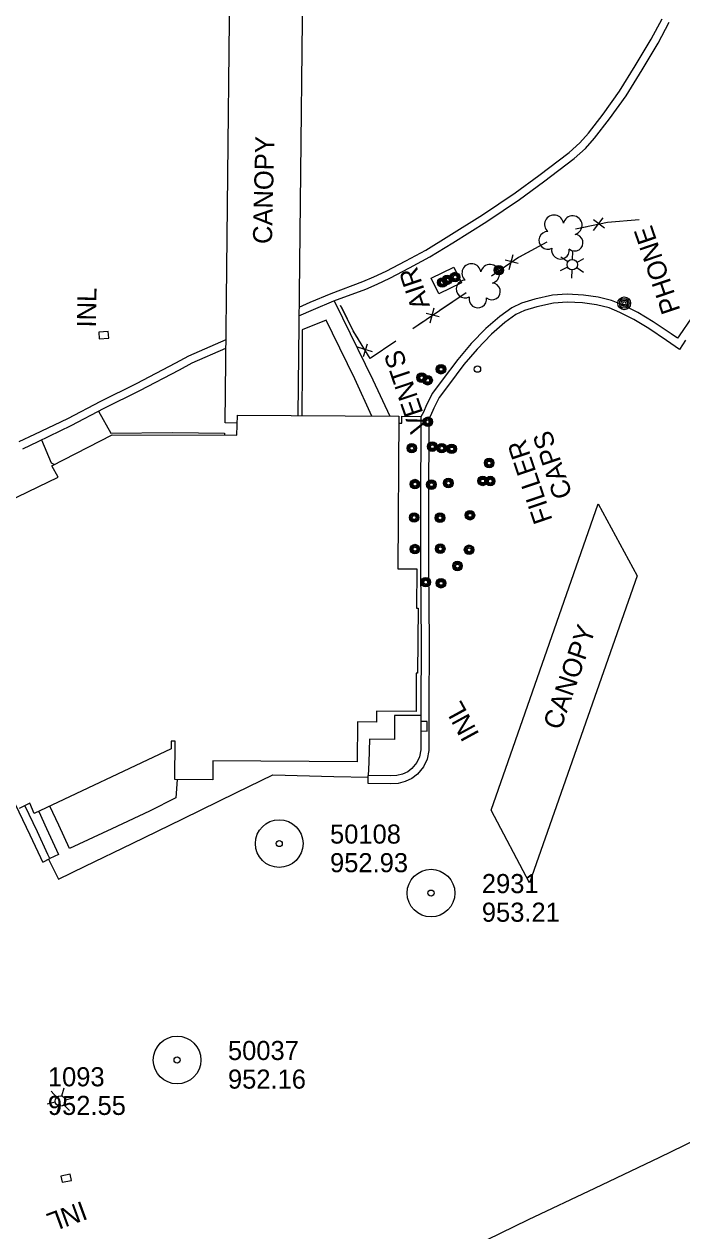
# Model space of a CAD drawing. Extents: x 353423 to 364002, y 127000 to 201942.
# Drawn here: x 358350.6 to 358557.6, y 132514.4 to 132893.9 of the extents above; entities that cross this region are included whole.
import ezdxf

# ---------------------------------------------------------------- set-up
doc = ezdxf.new("R2010")
doc.units = 0
for name, color, linetype in [('E_DTM_SlopeBottom', 7, 'Continuous'), ('E_FEN_Generic', 7, 'Continuous'), ('E_LAND_BrushLine', 7, 'Continuous'), ('E_MISCPROP', 7, 'Continuous'), ('E_RDWY_AsphConc', 7, 'Continuous'), ('E_UTL_ETransformer', 7, 'Continuous'), ('E_WTR_FlowLine', 7, 'Continuous')]:
    doc.layers.add(name, color=color, linetype=linetype)

msp = doc.modelspace()

# ---------------------------------------------------------------- linework, layer by layer
at = {"layer": 'E_DTM_SlopeBottom'}
for p, q in [((358532.67, 132832.95), (358529.69, 132829.02)), ((358533.16, 132829.74), (358529.78, 132832.28)), ((358504.39, 132821.34), (358503.16, 132816.56)), ((358506.08, 132818.57), (358501.98, 132819.6)), ((358481.18, 132801.8), (358477.09, 132802.88)), ((358479.52, 132804.58), (358478.23, 132799.82)), ((358460.23, 132790.86), (358455.53, 132792.34)), ((358457.38, 132789.31), (358458.63, 132793.35))]:
    msp.add_line(p, q, dxfattribs=at)
for points in [[(358544.08, 132832.32), (358534.2, 132831.49), (358524.13, 132829.41)], [(358544.08, 132832.32), (358534.2, 132831.49), (358534.16, 132831.48)], [(358527.71, 132830.15), (358524.13, 132829.41)], [(358515.08, 132825.32), (358506.17, 132820.45), (358497.64, 132814.59)], [(358515.08, 132825.32), (358506.34, 132820.54)], [(358500.9, 132816.83), (358497.64, 132814.59)], [(358489.72, 132809.33), (358472.88, 132798.04)], [(358489.72, 132809.33), (358481.45, 132803.78)], [(358467.52, 132794.17), (358459.49, 132788.74), (358454.18, 132797.43), (358450.19, 132805.43)], [(358450.62, 132804.57), (358450.19, 132805.43)], [(358455.92, 132794.58), (358454.18, 132797.43), (358450.62, 132804.57)], [(358475.98, 132800.12), (358472.88, 132798.04)], [(358377.21, 132795.17), (358377.07, 132797.17), (358374.08, 132796.96), (358374.22, 132794.96), (358377.21, 132795.17)], [(358467.52, 132794.17), (358459.49, 132788.74), (358459.35, 132788.96)], [(358477.44, 132674.59), (358475.44, 132674.6), (358475.42, 132671.6), (358477.42, 132671.59), (358477.44, 132674.59)], [(358365.49, 132530.24), (358365.13, 132532.2), (358362.18, 132531.66), (358362.54, 132529.69), (358365.49, 132530.24)]]:
    msp.add_lwpolyline(points, dxfattribs=at)
msp.add_lwpolyline([(358478.64, 132813.95), (358485.79, 132817.46), (358488.21, 132812.52), (358481.06, 132809.02)], close=True, dxfattribs=at)
at = {"layer": 'E_FEN_Generic'}
for centre, radius, start, end in [((358517.33, 132830.87), 2.97, 7.0782, 228.3121), ((358523.18, 132830.63), 2.97, 284.7291, 167.7023), ((358515.36, 132825.88), 2.78, 90.0491, 297.8221), ((358523.82, 132825.14), 2.61, 229.4343, 87.3669), ((358519.36, 132822.78), 2.78, 166.7261, 7.7372), ((358491.33, 132815.56), 2.97, 7.0782, 228.3121), ((358497.18, 132815.31), 2.97, 284.7291, 167.7023), ((358489.35, 132810.56), 2.78, 90.0491, 297.8221), ((358497.81, 132809.82), 2.61, 229.4343, 87.3669), ((358493.36, 132807.46), 2.78, 166.7261, 7.7372)]:
    msp.add_arc(centre, radius, start, end, dxfattribs=at)
at = {"layer": 'E_LAND_BrushLine'}
for p, q in [((358523.12, 132819.87), (358523.25, 132822.39)), ((358521.61, 132817.47), (358519.28, 132816.33)), ((358521.66, 132819.17), (358519.46, 132820.59)), ((358524.46, 132817.32), (358526.62, 132815.91)), ((358524.54, 132818.96), (358526.75, 132820.15)), ((358522.95, 132816.6), (358522.82, 132814)), ((358362.5, 132556.83), (358363.23, 132559.35)), ((358360.86, 132556.4), (358359.1, 132558.31)), ((358363.59, 132555.63), (358366.04, 132556.23)), ((358360.41, 132554.86), (358357.88, 132554.25)), ((358361.53, 132553.62), (358360.79, 132551.15)), ((358363.12, 132554.01), (358364.89, 132552.23))]:
    msp.add_line(p, q, dxfattribs=at)
for centre, radius in [((358523.06, 132818.23), 1.64), ((358539.42, 132806.09), 2.02), ((358539.41, 132806.09), 1.52), ((358539.45, 132806.1), 1.01), ((358539.44, 132806.1), 0.502), ((358362, 132555.23), 1.64)]:
    msp.add_circle(centre, radius, dxfattribs=at)
at = {"layer": 'E_MISCPROP'}
for points in [[(358437.08, 132802.11), (358441.6, 132804.13), (358448.08, 132806.83), (358458.12, 132810.57), (358461.7, 132812.11), (358465.66, 132813.98), (358471.85, 132817.19), (358478.26, 132820.67), (358485.52, 132825.13), (358496.17, 132831.84), (358506.5, 132838.73), (358514.05, 132844.23), (358523.68, 132851.58), (358527.24, 132854.8), (358530.08, 132857.98), (358534.83, 132864.04), (358540.04, 132871.36), (358545.04, 132879.45), (358550.1, 132887.92), (358553.59, 132894.45)], [(358437.11, 132804.87), (358440.61, 132806.43), (358447.16, 132809.15), (358457.19, 132812.89), (358460.67, 132814.39), (358464.55, 132816.22), (358470.67, 132819.4), (358477.01, 132822.84), (358484.2, 132827.25), (358494.81, 132833.94), (358505.07, 132840.78), (358512.55, 132846.24), (358522.08, 132853.5), (358525.46, 132856.57), (358528.16, 132859.59), (358532.83, 132865.54), (358537.96, 132872.74), (358542.91, 132880.75), (358547.92, 132889.15), (358551.34, 132895.54)], [(358448.16, 132806.86), (358450.77, 132801.46), (358460.3, 132782.06), (358465.71, 132770.6)], [(358558.73, 132794.45), (358556.83, 132791.58), (358552.76, 132794.36), (358547.14, 132798.17), (358542.45, 132801), (358538.05, 132803.22), (358534.65, 132804.62), (358530.73, 132805.57), (358526.34, 132806.18), (358521.49, 132806.47), (358517.18, 132806.13), (358511.91, 132805), (358507.99, 132803.82), (358505.34, 132802.53), (358501.82, 132800), (358497.64, 132796.33), (358493.14, 132791.71), (358489, 132786.86), (358484.08, 132780.39), (358481.19, 132776.51), (358479.48, 132773.12), (358478.49, 132770.74), (358477.94, 132769.73), (358477.93, 132766.43), (358477.85, 132745.7), (358477.79, 132722.84), (358478.05, 132699.46), (358477.97, 132678.72), (358477.93, 132673.32), (358477.91, 132665.48), (358477.4, 132662.75), (358476.28, 132660.33), (358474.39, 132657.98), (358472.56, 132656.63), (358470.49, 132655.67), (358468.28, 132655.11), (358466.03, 132655.02), (358458.82, 132655.09), (358458.84, 132657.59)], [(358560.57, 132801.47), (358556.66, 132795.85), (358556.15, 132795.07), (358554.17, 132796.43), (358548.49, 132800.28), (358543.66, 132803.19), (358539.09, 132805.49), (358535.43, 132807.01), (358531.19, 132808.03), (358526.59, 132808.67), (358521.47, 132808.98), (358516.82, 132808.61), (358511.29, 132807.43), (358507.07, 132806.16), (358504.05, 132804.68), (358500.26, 132801.95), (358495.92, 132798.14), (358491.29, 132793.4), (358487.05, 132788.43), (358482.08, 132781.89), (358479.06, 132777.83), (358477.21, 132774.16), (358476.23, 132771.82), (358475.44, 132770.36), (358475.43, 132766.43), (358475.35, 132745.71), (358475.29, 132722.83), (358475.55, 132699.46), (358475.47, 132678.74), (358475.43, 132673.33), (358475.41, 132665.72), (358475, 132663.52), (358474.14, 132661.66), (358472.64, 132659.8), (358471.28, 132658.79), (358469.65, 132658.04), (358467.91, 132657.59), (358465.99, 132657.52), (358458.84, 132657.59)], [(358459.99, 132770.64), (358454.7, 132782.29), (358447.67, 132796.68), (358445.65, 132800.8), (358438.04, 132797.79), (358438.12, 132786.15), (358437.96, 132770.79)], [(358398.3, 132787.4), (358402.37, 132789.58), (358414.13, 132794.73)], [(358399.47, 132785.2), (358403.46, 132787.32), (358414.1, 132791.98)], [(358349.06, 132762.58), (358353.93, 132764.89), (358364.31, 132769.86), (358374.69, 132775.32), (358385.91, 132780.9), (358398.31, 132787.41)], [(358350.19, 132760.35), (358355.01, 132762.63), (358365.43, 132767.63), (358375.83, 132773.1), (358387.04, 132778.68), (358399.47, 132785.2)], [(358374.02, 132772.14), (358377.92, 132765.21), (358397.23, 132765.42)], [(358468.53, 132768.35), (358469.49, 132768.34), (358469.48, 132770.6), (358475.5, 132770.46)], [(358397.23, 132765.42), (358413.65, 132765.25), (358413.62, 132764.58)], [(358356.03, 132763.12), (358359.07, 132755.87), (358360.15, 132755.42)], [(358475.45, 132676.5), (358467.13, 132676.48), (358467.11, 132668.93), (358459.28, 132669.07), (358459.04, 132661.68), (358458.84, 132657.59)], [(358356.48, 132630.37), (358355.81, 132631.7), (358352.52, 132638.85), (358346.75, 132650.94), (358342.83, 132659.44), (358339.86, 132665.43)], [(358400.48, 132643.93), (358417.43, 132652.29), (358428.83, 132657.77), (358448.01, 132657.33), (358458.84, 132657.09)], [(358398.77, 132656.35), (358398.36, 132650.54), (358390.01, 132646.36), (358378.21, 132640.8), (358364.9, 132634.64), (358361.54, 132642.02), (358358.71, 132647.99)], [(358356.48, 132630.37), (358358.71, 132631.49), (358358.06, 132632.78), (358354.78, 132639.91), (358350.84, 132648.17)], [(358355.19, 132646.33), (358357.67, 132640.9), (358361.4, 132632.81), (358358.71, 132631.49)], [(358358.26, 132631.27), (358361.43, 132625.05), (358369.82, 132629.07), (358384.54, 132636.22), (358400.48, 132643.93)], [(358401.35, 132465.83), (358421.21, 132475.14), (358447.67, 132488.04), (358469.88, 132498.6), (358491.87, 132509.5), (358509.27, 132517.94), (358530.2, 132527.85), (358550.67, 132537.59), (358569.86, 132546.9), (358589, 132555.99), (358607.79, 132564.98), (358625.03, 132573.36), (358635.49, 132578.04), (358639.01, 132579.73), (358643.78, 132582.85), (358652.7, 132589.43), (358657.24, 132593.33), (358660.23, 132597.03), (358665.84, 132605.99), (358673.95, 132620.21), (358675.37, 132622.86), (358675.49, 132623.86), (358675.13, 132626.43), (358673.22, 132639.8)]]:
    msp.add_lwpolyline(points, dxfattribs=at)
at = {"layer": 'E_RDWY_AsphConc'}
for centre, radius in [((358430.85, 132636.19), 7.5), ((358430.85, 132636.19), 7.5), ((358430.85, 132636.19), 7.5), ((358430.85, 132636.19), 7.5), ((358430.85, 132636.19), 0.96), ((358430.85, 132636.19), 0.96), ((358430.85, 132636.19), 0.96), ((358430.85, 132636.19), 0.96), ((358478.62, 132620.62), 7.5), ((358478.62, 132620.62), 7.5), ((358478.62, 132620.62), 7.5), ((358478.62, 132620.62), 7.5), ((358478.62, 132620.62), 0.96), ((358478.62, 132620.62), 0.96), ((358478.62, 132620.62), 0.96), ((358478.62, 132620.62), 0.96), ((358398.73, 132568.14), 7.5), ((358398.73, 132568.14), 7.5), ((358398.73, 132568.14), 7.5), ((358398.73, 132568.14), 7.5), ((358398.73, 132568.14), 0.96), ((358398.73, 132568.14), 0.96), ((358398.73, 132568.14), 0.96), ((358398.73, 132568.14), 0.96)]:
    msp.add_circle(centre, radius, dxfattribs=at)
at = {"layer": 'E_UTL_ETransformer'}
for centre, radius in [((358499.96, 132816.51), 1.5), ((358499.96, 132816.52), 1.22), ((358499.97, 132816.51), 0.968), ((358499.98, 132816.48), 0.605), ((358482.19, 132812.63), 1.5), ((358482.19, 132812.64), 1.22), ((358482.2, 132812.63), 0.968), ((358482.21, 132812.6), 0.605), ((358483.69, 132813.43), 1.5), ((358483.69, 132813.44), 1.22), ((358483.7, 132813.43), 0.968), ((358483.71, 132813.4), 0.605), ((358486.18, 132814.33), 1.5), ((358486.19, 132814.33), 1.22), ((358486.2, 132814.32), 0.968), ((358486.21, 132814.3), 0.605), ((358481.77, 132785.34), 1.5), ((358475.68, 132782.7), 1.5), ((358475.68, 132782.7), 1.22), ((358475.69, 132782.7), 0.968), ((358475.7, 132782.67), 0.605), ((358477.55, 132781.89), 1.5), ((358477.55, 132781.89), 1.22), ((358477.56, 132781.89), 0.968), ((358481.77, 132785.35), 1.22), ((358481.79, 132785.34), 0.968), ((358481.79, 132785.31), 0.605), ((358477.57, 132781.86), 0.605), ((358477.64, 132768.84), 1.5), ((358477.64, 132768.85), 1.22), ((358477.66, 132768.84), 0.968), ((358477.66, 132768.81), 0.605), ((358472.58, 132760.53), 1.5), ((358472.58, 132760.54), 1.22), ((358472.6, 132760.53), 0.968), ((358472.6, 132760.5), 0.605), ((358479.03, 132761.02), 1.5), ((358479.04, 132761.02), 1.22), ((358479.05, 132761.01), 0.968), ((358479.05, 132760.99), 0.605), ((358481.99, 132760.54), 1.5), ((358482, 132760.54), 1.22), ((358482.01, 132760.54), 0.968), ((358482.01, 132760.51), 0.605), ((358485.13, 132760.32), 1.5), ((358485.13, 132760.32), 1.22), ((358485.14, 132760.31), 0.968), ((358485.15, 132760.29), 0.605), ((358496.92, 132755.87), 1.5), ((358496.93, 132755.88), 1.22), ((358496.94, 132755.87), 0.968), ((358496.94, 132755.84), 0.605), ((358473.57, 132749.24), 1.5), ((358473.58, 132749.24), 1.22), ((358473.59, 132749.23), 0.968), ((358473.59, 132749.21), 0.605), ((358478.74, 132749.06), 1.5), ((358478.75, 132749.07), 1.22), ((358478.76, 132749.06), 0.968), ((358478.76, 132749.03), 0.605), ((358484.09, 132749.57), 1.5), ((358484.1, 132749.57), 1.22), ((358484.11, 132749.56), 0.968), ((358484.12, 132749.53), 0.605), ((358494.88, 132750.23), 1.5), ((358494.88, 132750.23), 1.22), ((358494.89, 132750.22), 0.968), ((358494.9, 132750.2), 0.605), ((358497.25, 132750.19), 1.5), ((358497.25, 132750.19), 1.22), ((358497.26, 132750.18), 0.968), ((358497.27, 132750.16), 0.605), ((358473.31, 132738.73), 1.5), ((358473.31, 132738.73), 1.22), ((358473.32, 132738.72), 0.968), ((358473.33, 132738.7), 0.605), ((358481.45, 132738.67), 1.5), ((358481.45, 132738.67), 1.22), ((358481.46, 132738.67), 0.968), ((358481.47, 132738.64), 0.605), ((358490.87, 132739.44), 1.5), ((358490.88, 132739.45), 1.22), ((358490.89, 132739.44), 0.968), ((358490.9, 132739.41), 0.605), ((358473.56, 132728.8), 1.5), ((358473.56, 132728.8), 1.22), ((358473.58, 132728.8), 0.968), ((358481.53, 132728.92), 1.5), ((358481.54, 132728.92), 1.22), ((358481.55, 132728.91), 0.968), ((358490.6, 132728.59), 1.5), ((358490.6, 132728.6), 1.22), ((358473.58, 132728.77), 0.605), ((358481.56, 132728.89), 0.605), ((358490.62, 132728.59), 0.968), ((358490.62, 132728.56), 0.605), ((358486.95, 132723.48), 1.5), ((358486.95, 132723.48), 1.22), ((358486.97, 132723.48), 0.968), ((358486.97, 132723.45), 0.605), ((358476.94, 132718.4), 1.5), ((358476.95, 132718.4), 1.22), ((358476.96, 132718.39), 0.968), ((358476.96, 132718.37), 0.605), ((358481.77, 132718.06), 1.5), ((358481.77, 132718.06), 1.22), ((358481.79, 132718.05), 0.968), ((358481.79, 132718.03), 0.605)]:
    msp.add_circle(centre, radius, dxfattribs=at)
at = {"layer": 'E_WTR_FlowLine'}
for points in [[(358417.69, 132768.44), (358413.86, 132768.48), (358415.27, 132904.89), (358438.14, 132904.65), (358436.76, 132770.8)], [(358310.42, 132726.84), (358361.28, 132751.37), (358359.3, 132754.99), (358378.32, 132764.69), (358417.56, 132764.57), (358417.77, 132770.93), (358468.54, 132770.58), (358468.21, 132722.58), (358474.17, 132722.54), (358474.08, 132710.24), (358474.56, 132710.24), (358474.42, 132689.78), (358473.99, 132689.78), (358473.91, 132677.77), (358461.49, 132677.86), (358461.46, 132674.4), (358455.47, 132674.45), (358455.39, 132661.94), (358409.96, 132662.26), (358409.92, 132656.28), (358398.01, 132656.36), (358398.09, 132668.44), (358396.84, 132668.45), (358396.82, 132665.98), (358353.78, 132645.67), (358353.78, 132645.67), (358352.35, 132648.94), (358349.01, 132647.24)]]:
    msp.add_lwpolyline(points, dxfattribs=at)
msp.add_lwpolyline([(358543.48, 132720.37), (358509.63, 132623.83), (358497.51, 132646.69), (358531.25, 132743.07)], close=True, dxfattribs=at)
msp.add_circle((358493.23, 132785.38), 1, dxfattribs=at)

# ---------------------------------------------------------------- texts
at = {"layer": 'E_DTM_SlopeBottom'}
for rotation, p in [(89.0214, (358373.17, 132798.43)), (118.6546, (358493.96, 132670.55)), (200.1741, (358368.93, 132523.9))]:
    msp.add_text('INL', height=6, rotation=rotation, dxfattribs=at).set_placement(p)
at = {"layer": 'E_LAND_BrushLine'}
for s, p in [('PHONE', (358557.15, 132803.93)), ('AIR', (358478.35, 132805.29)), ('VENTS', (358477.95, 132766.55))]:
    msp.add_text(s, height=6, rotation=108.6546, dxfattribs=at).set_placement(p)
at = {"layer": 'E_RDWY_AsphConc'}
for s, p in [('50108', (358446.85, 132636.19)), ('50108', (358446.85, 132636.19)), ('50108', (358446.85, 132636.19)), ('50108', (358446.85, 132636.19)), ('952.93', (358446.85, 132627.19)), ('952.93', (358446.85, 132627.19)), ('952.93', (358446.85, 132627.19)), ('952.93', (358446.85, 132627.19)), ('2931', (358494.62, 132620.62)), ('2931', (358494.62, 132620.62)), ('2931', (358494.62, 132620.62)), ('2931', (358494.62, 132620.62)), ('953.21', (358494.62, 132611.62)), ('953.21', (358494.62, 132611.62)), ('953.21', (358494.62, 132611.62)), ('953.21', (358494.62, 132611.62)), ('50037', (358414.73, 132568.14)), ('50037', (358414.73, 132568.14)), ('50037', (358414.73, 132568.14)), ('50037', (358414.73, 132568.14)), ('1093', (358358.07, 132559.87)), ('1093', (358358.07, 132559.87)), ('1093', (358358.07, 132559.87)), ('1093', (358358.07, 132559.87)), ('952.16', (358414.73, 132559.14)), ('952.16', (358414.73, 132559.14)), ('952.16', (358414.73, 132559.14)), ('952.16', (358414.73, 132559.14)), ('952.55', (358358.07, 132550.87)), ('952.55', (358358.07, 132550.87)), ('952.55', (358358.07, 132550.87)), ('952.55', (358358.07, 132550.87))]:
    msp.add_text(s, height=6, dxfattribs=at).set_placement(p)
at = {"layer": 'E_UTL_ETransformer'}
for s, p in [('CAPS', (358523.18, 132745.79)), ('FILLER', (358516.91, 132737.96))]:
    msp.add_text(s, height=6, rotation=108.6546, dxfattribs=at).set_placement(p)
at = {"layer": 'E_WTR_FlowLine'}
for rotation, p in [(88.6546, (358428.56, 132824.67)), (70.9106, (358519.42, 132671.61))]:
    msp.add_text('CANOPY', height=6, rotation=rotation, dxfattribs=at).set_placement(p)

doc.saveas('drawing.dxf')
